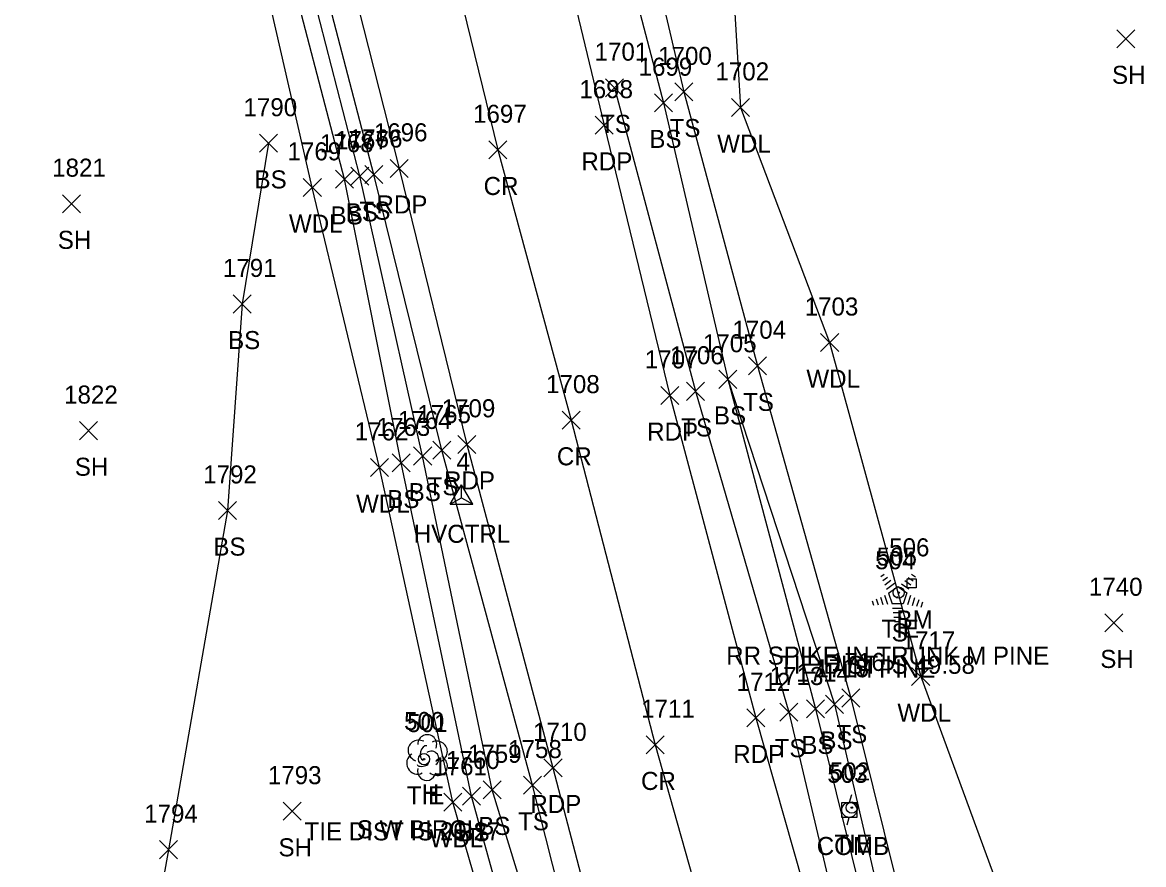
# Model space of a CAD drawing. Extents: x 1885914 to 1887218, y 756253 to 760620.
# Drawn here: x 1886409.9 to 1886534.2, y 759382.5 to 759475.9 of the extents above; entities that cross this region are included whole.
import ezdxf

# ---------------------------------------------------------------- set-up
doc = ezdxf.new("R2010")
doc.units = 0
for name, color, linetype in [('C_A', 7, 'Continuous'), ('C_C', 7, 'Continuous'), ('C_I', 7, 'Continuous'), ('CBP', 7, 'Continuous'), ('CPBM', 7, 'Continuous'), ('CPSM', 7, 'Continuous'), ('L_A', 7, 'Continuous'), ('L_C', 7, 'Continuous'), ('L_I', 7, 'Continuous'), ('L_TIC', 7, 'Continuous'), ('LAWA', 7, 'Continuous'), ('LELB', 7, 'Continuous'), ('LTC', 7, 'Continuous'), ('LTD', 7, 'Continuous'), ('P_A', 7, 'Continuous'), ('P_I', 7, 'Continuous'), ('P_TIC', 7, 'Continuous'), ('PET', 7, 'Continuous'), ('PRC', 7, 'Continuous'), ('U_A', 7, 'Continuous'), ('U_I', 7, 'Continuous'), ('UP', 7, 'Continuous')]:
    doc.layers.add(name, color=color, linetype=linetype)

msp = doc.modelspace()

# ---------------------------------------------------------------- linework, layer by layer
at = {"layer": 'CBP'}
for centre, radius in [((1886507.01, 759412.69), 0.625), ((1886507.01, 759412.69), 0.0833), ((1886454.39, 759394.23), 0.625), ((1886454.39, 759394.23), 0.0833), ((1886501.82, 759388.87), 0.625), ((1886501.82, 759388.87), 0.0833)]:
    msp.add_circle(centre, radius, dxfattribs=at)
at = {"layer": 'CPBM'}
for p, q in [((1886507.96, 759413.21), (1886507.96, 759414.21)), ((1886507.96, 759414.21), (1886508.96, 759414.21)), ((1886508.96, 759413.21), (1886507.96, 759413.21)), ((1886508.46, 759413.71), (1886508.46, 759413.71)), ((1886508.46, 759413.71), (1886508.46, 759413.71)), ((1886508.96, 759414.21), (1886508.96, 759413.21))]:
    msp.add_line(p, q, dxfattribs=at)
at = {"layer": 'CPSM'}
for p, q in [((1886457.3, 759422.49), (1886458.55, 759424.65)), ((1886457.3, 759422.49), (1886458.55, 759424.65)), ((1886457.3, 759422.49), (1886458.55, 759424.65)), ((1886459.8, 759422.49), (1886458.55, 759424.65)), ((1886458.55, 759423.21), (1886458.55, 759424.65)), ((1886459.8, 759422.49), (1886458.55, 759424.65)), ((1886458.55, 759423.21), (1886458.55, 759424.65)), ((1886459.8, 759422.49), (1886458.55, 759424.65)), ((1886458.55, 759423.21), (1886458.55, 759424.65)), ((1886457.3, 759422.49), (1886458.55, 759423.21)), ((1886457.3, 759422.49), (1886458.55, 759423.21)), ((1886457.3, 759422.49), (1886458.55, 759423.21)), ((1886458.55, 759423.21), (1886458.55, 759423.21)), ((1886458.55, 759423.21), (1886459.8, 759422.49)), ((1886458.55, 759423.21), (1886458.55, 759423.21)), ((1886458.55, 759423.21), (1886459.8, 759422.49)), ((1886458.55, 759423.21), (1886458.55, 759423.21)), ((1886458.55, 759423.21), (1886459.8, 759422.49)), ((1886457.3, 759422.49), (1886459.8, 759422.49)), ((1886457.3, 759422.49), (1886459.8, 759422.49)), ((1886457.3, 759422.49), (1886459.8, 759422.49))]:
    msp.add_line(p, q, dxfattribs=at)
at = {"layer": 'L_TIC'}
for points in [[(1886531.18, 759473.08), (1886533.18, 759475.08)], [(1886533.18, 759473.08), (1886531.18, 759475.08)], [(1886474.5, 759467.65), (1886476.5, 759469.65)], [(1886476.5, 759467.65), (1886474.5, 759469.65)], [(1886482.21, 759467.18), (1886484.21, 759469.18)], [(1886484.21, 759467.18), (1886482.21, 759469.18)], [(1886482.21, 759467.18), (1886484.21, 759469.18)], [(1886484.21, 759467.18), (1886482.21, 759469.18)], [(1886479.93, 759465.98), (1886481.93, 759467.98)], [(1886481.93, 759465.98), (1886479.93, 759467.98)], [(1886488.47, 759465.46), (1886490.47, 759467.46)], [(1886490.47, 759465.46), (1886488.47, 759467.46)], [(1886436.16, 759461.49), (1886438.16, 759463.49)], [(1886438.16, 759461.49), (1886436.16, 759463.49)], [(1886444.59, 759457.5), (1886446.59, 759459.5)], [(1886446.59, 759457.5), (1886444.59, 759459.5)], [(1886446.27, 759457.84), (1886448.27, 759459.84)], [(1886448.27, 759457.84), (1886446.27, 759459.84)], [(1886447.84, 759458.02), (1886449.84, 759460.02)], [(1886449.84, 759458.02), (1886447.84, 759460.02)], [(1886441.01, 759456.6), (1886443.01, 759458.6)], [(1886443.01, 759456.6), (1886441.01, 759458.6)], [(1886414.3, 759454.79), (1886416.3, 759456.79)], [(1886416.3, 759454.79), (1886414.3, 759456.79)], [(1886433.23, 759443.68), (1886435.23, 759445.68)], [(1886435.23, 759443.68), (1886433.23, 759445.68)], [(1886498.36, 759439.4), (1886500.36, 759441.4)], [(1886500.36, 759439.4), (1886498.36, 759441.4)], [(1886490.35, 759436.83), (1886492.35, 759438.83)], [(1886492.35, 759436.83), (1886490.35, 759438.83)], [(1886487.08, 759435.33), (1886489.08, 759437.33)], [(1886489.08, 759435.33), (1886487.08, 759437.33)], [(1886487.08, 759435.33), (1886489.08, 759437.33)], [(1886489.08, 759435.33), (1886487.08, 759437.33)], [(1886483.5, 759434), (1886485.5, 759436)], [(1886485.5, 759434), (1886483.5, 759436)], [(1886416.19, 759429.64), (1886418.19, 759431.64)], [(1886418.19, 759429.64), (1886416.19, 759431.64)], [(1886455.38, 759427.48), (1886457.38, 759429.48)], [(1886457.38, 759427.48), (1886455.38, 759429.48)], [(1886450.87, 759426.06), (1886452.87, 759428.06)], [(1886452.87, 759426.06), (1886450.87, 759428.06)], [(1886453.24, 759426.83), (1886455.24, 759428.83)], [(1886455.24, 759426.83), (1886453.24, 759428.83)], [(1886448.45, 759425.56), (1886450.45, 759427.56)], [(1886450.45, 759425.56), (1886448.45, 759427.56)], [(1886431.6, 759420.79), (1886433.6, 759422.79)], [(1886433.6, 759420.79), (1886431.6, 759422.79)], [(1886529.87, 759408.34), (1886531.87, 759410.34)], [(1886531.87, 759408.34), (1886529.87, 759410.34)], [(1886508.45, 759402.39), (1886510.45, 759404.39)], [(1886510.45, 759402.39), (1886508.45, 759404.39)], [(1886500.7, 759400.01), (1886502.7, 759402.01)], [(1886502.7, 759400.01), (1886500.7, 759402.01)], [(1886496.78, 759398.81), (1886498.78, 759400.81)], [(1886498.78, 759398.81), (1886496.78, 759400.81)], [(1886498.89, 759399.31), (1886500.89, 759401.31)], [(1886500.89, 759399.31), (1886498.89, 759401.31)], [(1886493.85, 759398.45), (1886495.85, 759400.45)], [(1886495.85, 759398.45), (1886493.85, 759400.45)], [(1886465.41, 759390.35), (1886467.41, 759392.35)], [(1886467.41, 759390.35), (1886465.41, 759392.35)], [(1886458.66, 759389.14), (1886460.66, 759391.14)], [(1886460.66, 759389.14), (1886458.66, 759391.14)], [(1886460.96, 759389.83), (1886462.96, 759391.83)], [(1886462.96, 759389.83), (1886460.96, 759391.83)], [(1886456.59, 759388.45), (1886458.59, 759390.45)], [(1886458.59, 759388.45), (1886456.59, 759390.45)], [(1886438.77, 759387.46), (1886440.77, 759389.46)], [(1886440.77, 759387.46), (1886438.77, 759389.46)], [(1886425.06, 759383.2), (1886427.06, 759385.2)], [(1886427.06, 759383.2), (1886425.06, 759385.2)]]:
    msp.add_lwpolyline(points, dxfattribs=at)
at = {"layer": 'LAWA'}
for points in [[(1886460.31, 759591.25), (1886468.58, 759565.01), (1886481.47, 759530.19), (1886487.24, 759503.98), (1886489.47, 759466.46), (1886499.36, 759440.4), (1886509.45, 759403.39), (1886522.87, 759366.86), (1886528.37, 759345.25)], [(1886474.03, 759328.22), (1886466.13, 759359.95), (1886457.59, 759389.45), (1886449.45, 759426.56), (1886442.01, 759457.6), (1886435.91, 759484.2), (1886428.83, 759514.65), (1886425.07, 759533.66), (1886420.25, 759558.57), (1886411.95, 759586.16)]]:
    msp.add_lwpolyline(points, dxfattribs=at)
at = {"layer": 'LELB'}
for points in [[(1886482.43, 759330.53), (1886473.8, 759362.16), (1886466.41, 759391.35), (1886456.38, 759428.48), (1886448.84, 759459.02), (1886441.76, 759486.12), (1886435.76, 759515.56), (1886431.42, 759535.05), (1886426.06, 759559.46), (1886421.11, 759588.4), (1886418.79, 759606.26), (1886412.24, 759623.91), (1886411.78, 759647.7), (1886414.35, 759668.8), (1886416.75, 759691.58), (1886420.37, 759713.7), (1886423.9, 759735.67), (1886428.12, 759754.98), (1886431.72, 759778.14), (1886436.25, 759795.18), (1886439.73, 759830.38)], [(1886479.66, 759329.52), (1886471.03, 759361.21), (1886461.96, 759390.83), (1886454.24, 759427.83), (1886447.27, 759458.84), (1886440.35, 759485.71), (1886434.88, 759515.3), (1886430.89, 759534.99), (1886424.93, 759559.47), (1886417.7, 759587.99), (1886415.39, 759606.58), (1886409.44, 759622.11), (1886408.97, 759647.11), (1886405.32, 759668.25), (1886398.3, 759701.89), (1886401.43, 759725.45)], [(1886476.45, 759328.91), (1886467.85, 759360.49), (1886459.66, 759390.14), (1886451.87, 759427.06), (1886445.59, 759458.5), (1886438.66, 759485.01), (1886433.8, 759515.01), (1886429.52, 759534.9), (1886422.3, 759559.11), (1886414.83, 759587.35), (1886411.02, 759591.73), (1886403.8, 759605.65), (1886400.43, 759619.74), (1886399.2, 759644.65), (1886399.26, 759666.38)], [(1886456.79, 759611.09), (1886455.06, 759603.13), (1886455.4, 759590.3), (1886459.57, 759560.59), (1886463.53, 759534.18), (1886472.77, 759498.14), (1886480.93, 759466.98), (1886488.08, 759436.33), (1886497.78, 759399.81), (1886507.53, 759360.15), (1886514.24, 759339.59)], [(1886468.58, 759565.01), (1886469.5, 759531.39), (1886475.96, 759499.09), (1886483.21, 759468.18)], [(1886475.5, 759468.65), (1886484.5, 759435), (1886494.85, 759399.45), (1886504.42, 759358.96), (1886510.54, 759338.61)], [(1886483.21, 759468.18), (1886491.35, 759437.83), (1886501.7, 759401.01), (1886511.44, 759361.83), (1886517.67, 759340.46)], [(1886437.16, 759462.49), (1886434.23, 759444.68), (1886432.6, 759421.79), (1886426.06, 759384.2), (1886419.42, 759347.38), (1886420.7, 759313.02)], [(1886488.08, 759436.33), (1886499.89, 759400.31), (1886509.06, 759360.87), (1886515.61, 759339.89)]]:
    msp.add_lwpolyline(points, dxfattribs=at)
at = {"layer": 'LTC'}
for p, q in [((1886505.04, 759414.49), (1886505.39, 759414.75)), ((1886505.25, 759414.02), (1886505.78, 759414.41)), ((1886508.07, 759414.38), (1886508.62, 759413.98)), ((1886508.44, 759414.73), (1886508.86, 759414.43)), ((1886505.46, 759413.56), (1886506.16, 759414.07)), ((1886505.67, 759413.09), (1886506.55, 759413.73)), ((1886505.89, 759412.64), (1886506.9, 759413.37)), ((1886506.9, 759413.37), (1886507.9, 759412.65)), ((1886507.32, 759413.68), (1886508.13, 759413.1)), ((1886507.69, 759414.03), (1886508.37, 759413.54)), ((1886504.53, 759411.99), (1886504.74, 759411.33)), ((1886504.98, 759412.2), (1886505.25, 759411.37)), ((1886505.44, 759412.42), (1886505.77, 759411.4)), ((1886505.89, 759412.64), (1886506.28, 759411.44)), ((1886507.9, 759412.65), (1886507.51, 759411.44)), ((1886508.34, 759412.38), (1886508, 759411.34)), ((1886508.78, 759412.13), (1886508.5, 759411.24)), ((1886509.23, 759411.88), (1886508.99, 759411.15)), ((1886504.07, 759411.77), (1886504.22, 759411.3)), ((1886507.51, 759411.44), (1886506.28, 759411.44)), ((1886507.47, 759410.94), (1886506.33, 759410.94)), ((1886509.67, 759411.63), (1886509.48, 759411.05)), ((1886507.39, 759410.44), (1886506.4, 759410.44)), ((1886507.3, 759409.94), (1886506.47, 759409.94)), ((1886507.22, 759409.44), (1886506.54, 759409.44))]:
    msp.add_line(p, q, dxfattribs=at)
at = {"layer": 'LTD'}
msp.add_line((1886454.71, 759394.46), (1886454.71, 759394.46), dxfattribs=at)
msp.add_line((1886454.71, 759394.46), (1886454.71, 759394.46), dxfattribs=at)
msp.add_arc((1886454.75, 759395.89), 1.05, 335.5272, 180.9563, dxfattribs=at)
for centre, major_axis, ratio, start_param, end_param in [((1886453.91, 759395.13), (1.21, -0.51), 0.895232, 1.570796, 4.712389), ((1886454.5, 759394.92), (-0.208, -0.792), 0.645439, 3.141593, 6.283185), ((1886455.75, 759395.04), (-1.14, -0.48), 0.949671, 1.570796, 4.712389), ((1886453.62, 759393.75), (0.58, -1.04), 0.959034, 3.141593, 6.283185), ((1886455.21, 759394.29), (-0.5, 0.667), 0.989748, 3.141593, 6.283185), ((1886455.71, 759393.63), (-1.09, 0.79), 0.841452, 1.570796, 4.712389), ((1886454.25, 759393.71), (-0.625, -0.083), 0.423636, 0, 3.141593), ((1886454.71, 759392.96), (0.26, 1.06), 0.942809, 1.570796, 4.712389)]:
    msp.add_ellipse(centre, major_axis=major_axis, ratio=ratio, start_param=start_param, end_param=end_param, dxfattribs=at)
at = {"layer": 'P_TIC'}
for points in [[(1886473.35, 759463.49), (1886475.35, 759465.49)], [(1886475.35, 759463.49), (1886473.35, 759465.49)], [(1886461.57, 759460.76), (1886463.57, 759462.76)], [(1886463.57, 759460.76), (1886461.57, 759462.76)], [(1886450.63, 759458.71), (1886452.63, 759460.71)], [(1886452.63, 759458.71), (1886450.63, 759460.71)], [(1886480.64, 759433.54), (1886482.64, 759435.54)], [(1886482.64, 759433.54), (1886480.64, 759435.54)], [(1886469.69, 759430.8), (1886471.69, 759432.8)], [(1886471.69, 759430.8), (1886469.69, 759432.8)], [(1886458.13, 759428.12), (1886460.13, 759430.12)], [(1886460.13, 759428.12), (1886458.13, 759430.12)], [(1886490.18, 759397.8), (1886492.18, 759399.8)], [(1886492.18, 759397.8), (1886490.18, 759399.8)], [(1886479.02, 759394.82), (1886481.02, 759396.82)], [(1886481.02, 759394.82), (1886479.02, 759396.82)], [(1886467.69, 759392.26), (1886469.69, 759394.26)], [(1886469.69, 759392.26), (1886467.69, 759394.26)]]:
    msp.add_lwpolyline(points, dxfattribs=at)
at = {"layer": 'PET'}
for points in [[(1886505.21, 759975.04), (1886485.32, 759931.76), (1886475.82, 759908.45), (1886466.13, 759882.96), (1886456.93, 759855.61), (1886449.99, 759833.06), (1886442.98, 759808.26), (1886435.87, 759778.49), (1886430.37, 759752.23), (1886424.92, 759721.57), (1886422.03, 759696.27), (1886420.3, 759670.71), (1886419.91, 759641.82), (1886421.23, 759616.47), (1886424.6, 759585.72), (1886430.09, 759554.32), (1886435.19, 759528.63), (1886443.72, 759490.84), (1886451.63, 759459.71), (1886459.13, 759429.12), (1886468.69, 759393.26), (1886479.71, 759351.07), (1886485.06, 759331.17)], [(1886526.14, 759964.92), (1886507.07, 759922.75), (1886498.17, 759900.86), (1886488.16, 759874.15), (1886479.62, 759848.04), (1886473, 759827.05), (1886466.37, 759803.11), (1886458.99, 759773.42), (1886453.36, 759746.97), (1886448.76, 759720.11), (1886445.71, 759693.61), (1886444.44, 759668.96), (1886443.78, 759643.55), (1886445.31, 759617.59), (1886448.26, 759589.04), (1886453.63, 759558.69), (1886458.27, 759533.55), (1886466.8, 759496), (1886474.35, 759464.49), (1886481.64, 759434.54), (1886491.18, 759398.8), (1886502.68, 759358.39), (1886508.23, 759337.95)]]:
    msp.add_lwpolyline(points, dxfattribs=at)
at = {"layer": 'PRC'}
msp.add_lwpolyline([(1886516.05, 759969.43), (1886496.99, 759926.69), (1886487.66, 759904.2), (1886477.68, 759877.96), (1886468.59, 759851.92), (1886461.77, 759829.93), (1886454.6, 759805.62), (1886447.16, 759775.82), (1886441.74, 759748.8), (1886436.89, 759720.56), (1886434.02, 759695.25), (1886432.32, 759669.09), (1886432.26, 759642.82), (1886433.77, 759616.6), (1886436.98, 759587.84), (1886441.74, 759556.93), (1886446.53, 759531.43), (1886454.86, 759493.34), (1886462.57, 759461.76), (1886470.69, 759431.8), (1886480.02, 759395.82), (1886491.53, 759354.96), (1886496.99, 759335.08)], dxfattribs=at)
at = {"layer": 'UP'}
for p, q in [((1886501.79, 759390.28), (1886501.54, 759389.44)), ((1886500.71, 759387.78), (1886500.71, 759389.44)), ((1886500.71, 759389.44), (1886502.38, 759389.44)), ((1886501.54, 759388.61), (1886501.54, 759388.61)), ((1886502.38, 759389.44), (1886502.38, 759387.78)), ((1886502.38, 759387.78), (1886500.71, 759387.78)), ((1886501.29, 759386.94), (1886501.54, 759387.78))]:
    msp.add_line(p, q, dxfattribs=at)
msp.add_circle((1886501.54, 759388.61), 0.833, dxfattribs=at)

# ---------------------------------------------------------------- texts
at = {"layer": 'C_A'}
for s, p in [('HVCTRL', (1886453.25, 759418.21)), ('HVCTRL', (1886453.25, 759418.21)), ('HVCTRL', (1886453.25, 759418.21)), ('BM', (1886506.77, 759408.71)), ('TIE', (1886505.09, 759407.69)), ('TIE', (1886452.47, 759389.23)), ('TIE', (1886499.9, 759383.87))]:
    msp.add_text(s, height=2, dxfattribs=at).set_placement(p)
at = {"layer": 'C_C'}
for s, p in [('RR SPIKE IN TRUNK M PINE', (1886487.89, 759404.71)), ('TIE DIST IS 49.58', (1886493.76, 759403.69)), ('TIE DIST IS 29.27', (1886441.15, 759385.23))]:
    msp.add_text(s, height=2, dxfattribs=at).set_placement(p)
at = {"layer": 'C_I'}
for s, p in [('4', (1886457.99, 759426.21)), ('4', (1886457.99, 759426.21)), ('4', (1886457.99, 759426.21)), ('506', (1886505.96, 759416.71)), ('505', (1886504.57, 759415.69)), ('501', (1886452.52, 759397.23)), ('502', (1886499.38, 759391.87))]:
    msp.add_text(s, height=2, dxfattribs=at).set_placement(p)
at = {"layer": 'L_A'}
for s, p in [('SH', (1886530.66, 759469.08)), ('TS', (1886473.91, 759463.65)), ('TS', (1886481.62, 759463.18)), ('TS', (1886481.62, 759463.18)), ('BS', (1886479.37, 759461.98)), ('WDL', (1886486.89, 759461.46)), ('BS', (1886435.6, 759457.49)), ('BS', (1886444.03, 759453.5)), ('BS', (1886445.71, 759453.84)), ('TS', (1886447.25, 759454.02)), ('WDL', (1886439.42, 759452.6)), ('SH', (1886413.79, 759450.79)), ('BS', (1886432.67, 759439.68)), ('WDL', (1886496.78, 759435.4)), ('TS', (1886489.76, 759432.83)), ('BS', (1886486.53, 759431.33)), ('BS', (1886486.53, 759431.33)), ('TS', (1886482.91, 759430)), ('SH', (1886415.68, 759425.64)), ('BS', (1886452.69, 759422.83)), ('TS', (1886454.79, 759423.48)), ('WDL', (1886446.86, 759421.56)), ('BS', (1886450.31, 759422.06)), ('BS', (1886431.04, 759416.79)), ('S', (1886506.23, 759407.28)), ('SH', (1886529.36, 759404.34)), ('WDL', (1886506.87, 759398.39)), ('BS', (1886498.33, 759395.31)), ('TS', (1886500.11, 759396.01)), ('TS', (1886493.26, 759394.45)), ('BS', (1886496.22, 759394.81)), ('H', (1886454.14, 759389.46)), ('TS', (1886464.82, 759386.35)), ('BS', (1886458.1, 759385.14)), ('BS', (1886460.4, 759385.83)), ('WDL', (1886455.01, 759384.45)), ('SH', (1886438.26, 759383.46))]:
    msp.add_text(s, height=2, dxfattribs=at).set_placement(p)
at = {"layer": 'L_C'}
for s, p in [('M PINE', (1886501.87, 759403.28)), ('S W BIRCH', (1886446.94, 759385.46))]:
    msp.add_text(s, height=2, dxfattribs=at).set_placement(p)
at = {"layer": 'L_I'}
for s, p in [('1701', (1886473.3, 759471.65)), ('1700', (1886480.35, 759471.18)), ('1700', (1886480.35, 759471.18)), ('1699', (1886478.18, 759469.98)), ('1702', (1886486.7, 759469.46)), ('1790', (1886434.38, 759465.49)), ('1768', (1886442.85, 759461.5)), ('1767', (1886444.53, 759461.84)), ('1766', (1886446.05, 759462.02)), ('1769', (1886439.26, 759460.6)), ('1821', (1886413.17, 759458.79)), ('1791', (1886432.1, 759447.68)), ('1703', (1886496.59, 759443.4)), ('1704', (1886488.58, 759440.83)), ('1705', (1886485.31, 759439.33)), ('1705', (1886485.31, 759439.33)), ('1706', (1886481.67, 759438)), ('1822', (1886414.49, 759433.64)), ('1765', (1886453.64, 759431.48)), ('1763', (1886449.13, 759430.06)), ('1764', (1886451.5, 759430.83)), ('1762', (1886446.71, 759429.56)), ('1792', (1886429.91, 759424.79)), ('504', (1886504.4, 759415.28)), ('1740', (1886528.1, 759412.34)), ('1717', (1886507.33, 759406.39)), ('1716', (1886499.52, 759404.01)), ('1713', (1886492.72, 759402.45)), ('1714', (1886495.65, 759402.81)), ('1715', (1886497.77, 759403.31)), ('500', (1886452.18, 759397.46)), ('1759', (1886459.26, 759393.83)), ('1758', (1886463.72, 759394.35)), ('1761', (1886455.42, 759392.45)), ('1760', (1886456.83, 759393.14)), ('1793', (1886437.08, 759391.46)), ('1794', (1886423.37, 759387.2))]:
    msp.add_text(s, height=2, dxfattribs=at).set_placement(p)
at = {"layer": 'LTC'}
msp.add_text('.', height=1.04, rotation=270, dxfattribs=at).set_placement((1886506.79, 759412.39))
at = {"layer": 'P_A'}
for s, p in [('RDP', (1886471.84, 759459.49)), ('CR', (1886461, 759456.76)), ('RDP', (1886449.12, 759454.71)), ('RDP', (1886479.13, 759429.54)), ('CR', (1886469.12, 759426.8)), ('RDP', (1886456.61, 759424.12)), ('RDP', (1886488.67, 759393.8)), ('CR', (1886478.45, 759390.82)), ('RDP', (1886466.18, 759388.26))]:
    msp.add_text(s, height=2, dxfattribs=at).set_placement(p)
at = {"layer": 'P_I'}
for s, p in [('1698', (1886471.61, 759467.49)), ('1697', (1886459.83, 759464.76)), ('1696', (1886448.83, 759462.71)), ('1707', (1886478.87, 759437.54)), ('1708', (1886467.92, 759434.8)), ('1709', (1886456.35, 759432.12)), ('1712', (1886489.05, 759401.8)), ('1711', (1886478.46, 759398.82)), ('1710', (1886466.48, 759396.26))]:
    msp.add_text(s, height=2, dxfattribs=at).set_placement(p)
at = {"layer": 'U_A'}
msp.add_text('COMB', height=2, dxfattribs=at).set_placement((1886497.93, 759383.61))
at = {"layer": 'U_I'}
msp.add_text('503', height=2, dxfattribs=at).set_placement((1886499.1, 759391.61))

doc.saveas('drawing.dxf')
